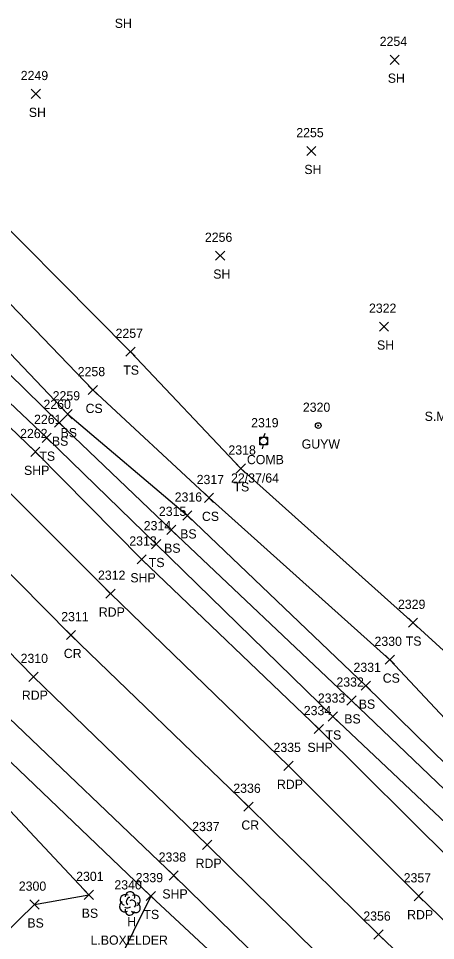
# Model space of a CAD drawing. Extents: x 1472233 to 1475777, y 540726 to 543442.
# Drawn here: x 1473588 to 1473678.6, y 542599.7 to 542800 of the extents above; entities that cross this region are included whole.
import ezdxf

# ---------------------------------------------------------------- set-up
doc = ezdxf.new("R2010")
doc.units = 0
for name, color, linetype in [('L_A', 7, 'Continuous'), ('L_C', 7, 'Continuous'), ('L_I', 7, 'Continuous'), ('L_TIC', 7, 'Continuous'), ('LELB', 7, 'Continuous'), ('LTD', 7, 'Continuous'), ('P_A', 7, 'Continuous'), ('P_I', 7, 'Continuous'), ('P_TIC', 7, 'Continuous'), ('PET', 7, 'Continuous'), ('PRC', 7, 'Continuous'), ('PSP', 7, 'Continuous'), ('U_A', 7, 'Continuous'), ('U_C', 7, 'Continuous'), ('U_I', 7, 'Continuous'), ('UP', 7, 'Continuous'), ('UPGW', 7, 'Continuous')]:
    doc.layers.add(name, color=color, linetype=linetype)

msp = doc.modelspace()

# ---------------------------------------------------------------- linework, layer by layer
at = {"layer": 'L_TIC'}
for points in [[(1473668.73, 542790.01), (1473670.73, 542792.01)], [(1473670.73, 542790.01), (1473668.73, 542792.01)], [(1473590.8, 542782.59), (1473592.8, 542784.59)], [(1473592.8, 542782.59), (1473590.8, 542784.59)], [(1473650.62, 542770.19), (1473652.62, 542772.19)], [(1473652.62, 542770.19), (1473650.62, 542772.19)], [(1473630.84, 542747.47), (1473632.84, 542749.47)], [(1473632.84, 542747.47), (1473630.84, 542749.47)], [(1473666.4, 542732.06), (1473668.4, 542734.06)], [(1473668.4, 542732.06), (1473666.4, 542734.06)], [(1473611.39, 542726.62), (1473613.39, 542728.62)], [(1473613.39, 542726.62), (1473611.39, 542728.62)], [(1473603.17, 542718.3), (1473605.17, 542720.3)], [(1473605.17, 542718.3), (1473603.17, 542720.3)], [(1473597.73, 542713.04), (1473599.73, 542715.04)], [(1473599.73, 542713.04), (1473597.73, 542715.04)], [(1473595.86, 542711.19), (1473597.86, 542713.19)], [(1473597.86, 542711.19), (1473595.86, 542713.19)], [(1473593.17, 542707.93), (1473595.17, 542709.93)], [(1473595.17, 542707.93), (1473593.17, 542709.93)], [(1473635.32, 542701.27), (1473637.32, 542703.27)], [(1473637.32, 542701.27), (1473635.32, 542703.27)], [(1473628.42, 542694.86), (1473630.42, 542696.86)], [(1473630.42, 542694.86), (1473628.42, 542696.86)], [(1473623.71, 542691.05), (1473625.71, 542693.05)], [(1473625.71, 542691.05), (1473623.71, 542693.05)], [(1473620.23, 542687.95), (1473622.23, 542689.95)], [(1473622.23, 542687.95), (1473620.23, 542689.95)], [(1473616.93, 542684.84), (1473618.93, 542686.84)], [(1473618.93, 542684.84), (1473616.93, 542686.84)], [(1473672.71, 542667.77), (1473674.71, 542669.77)], [(1473674.71, 542667.77), (1473672.71, 542669.77)], [(1473667.69, 542659.73), (1473669.69, 542661.73)], [(1473669.69, 542659.73), (1473667.69, 542661.73)], [(1473662.48, 542654.08), (1473664.48, 542656.08)], [(1473664.48, 542654.08), (1473662.48, 542656.08)], [(1473659.33, 542650.88), (1473661.33, 542652.88)], [(1473661.33, 542650.88), (1473659.33, 542652.88)], [(1473655.3, 542647.39), (1473657.3, 542649.39)], [(1473657.3, 542647.39), (1473655.3, 542649.39)], [(1473602.34, 542608.68), (1473604.34, 542610.68)], [(1473604.34, 542608.68), (1473602.34, 542610.68)], [(1473615.76, 542608.41), (1473617.76, 542610.41)], [(1473617.76, 542608.41), (1473615.76, 542610.41)], [(1473615.76, 542608.41), (1473617.76, 542610.41)], [(1473617.76, 542608.41), (1473615.76, 542610.41)], [(1473590.54, 542606.56), (1473592.54, 542608.56)], [(1473592.54, 542606.56), (1473590.54, 542608.56)]]:
    msp.add_lwpolyline(points, dxfattribs=at)
at = {"layer": 'LELB'}
for points in [[(1473533.67, 542804.55), (1473552.88, 542788.13), (1473556.88, 542785.23), (1473573.99, 542766.25), (1473612.39, 542727.62), (1473636.32, 542702.27), (1473673.71, 542668.77), (1473704.07, 542641.06), (1473731.53, 542612.73), (1473761.48, 542585.32), (1473782.29, 542564.92), (1473785.92, 542561.45), (1473799.65, 542550.04), (1473837.85, 542540.63), (1473852.25, 542543.24), (1473872.66, 542564.42), (1473894.27, 542588.71), (1473912.61, 542619.34)], [(1473525.71, 542797.41), (1473571.76, 542752.99), (1473604.17, 542719.3), (1473629.42, 542695.86), (1473668.69, 542660.73), (1473695.91, 542631.66), (1473722.49, 542604.9), (1473754.1, 542577.93), (1473792.77, 542542.66), (1473824.81, 542525.66)], [(1473520.98, 542792.82), (1473566.75, 542747.64), (1473598.73, 542714.04), (1473624.71, 542692.05), (1473663.48, 542655.08), (1473691.76, 542627.35), (1473719.38, 542602.08), (1473749.67, 542574.18), (1473788.77, 542538.46), (1473824.81, 542525.66), (1473852.8, 542532.76), (1473882.6, 542548.46), (1473905.87, 542578.34), (1473927.53, 542599.64)], [(1473518.4, 542790.01), (1473563.89, 542744.47), (1473596.86, 542712.19), (1473621.23, 542688.95), (1473660.33, 542651.88), (1473689.02, 542624.42), (1473715.73, 542598.61), (1473746.44, 542571.32), (1473784.75, 542534.69), (1473817.99, 542514.69), (1473848.43, 542502.42), (1473876.97, 542512.66), (1473897.43, 542533.79), (1473923.6, 542558.96), (1473938.44, 542588.81), (1473927.53, 542599.64)], [(1473514.27, 542786.32), (1473560.24, 542740.99), (1473594.17, 542708.93), (1473617.93, 542685.84), (1473656.3, 542648.39), (1473686.09, 542620.25), (1473711.9, 542594.5), (1473742.08, 542567.84), (1473780.05, 542529.89), (1473807.97, 542506.72), (1473829.24, 542487.77), (1473845.46, 542486.06), (1473857.71, 542489.19), (1473866.44, 542494.63), (1473880.47, 542509.49), (1473900.34, 542530.71), (1473925.82, 542557.03), (1473946.47, 542580.98), (1473946.59, 542594.08), (1473931.4, 542613.43), (1473912.61, 542619.34)], [(1473565.52, 542656.42), (1473579.67, 542644.83), (1473616.76, 542609.41), (1473646.96, 542581.33), (1473673.23, 542554.38), (1473676.6, 542547.7)], [(1473566.89, 542528.89), (1473564.41, 542543.6), (1473559.82, 542572.3), (1473573.83, 542590.3), (1473591.54, 542607.56), (1473603.34, 542609.68), (1473581.89, 542632.49), (1473565.16, 542641.39)], [(1473616.76, 542609.41), (1473601.51, 542578.57), (1473587.91, 542551.82), (1473580.91, 542527.84)]]:
    msp.add_lwpolyline(points, dxfattribs=at)
at = {"layer": 'LTD'}
msp.add_line((1473612.22, 542607.84), (1473612.22, 542607.84), dxfattribs=at)
msp.add_line((1473612.22, 542607.84), (1473612.22, 542607.84), dxfattribs=at)
msp.add_arc((1473612.27, 542609.28), 1.05, 335.5272, 180.9563, dxfattribs=at)
for centre, major_axis, ratio, start_param, end_param in [((1473611.14, 542607.14), (0.58, -1.04), 0.959034, 3.141593, 6.283185), ((1473611.43, 542608.51), (1.21, -0.51), 0.895232, 1.570796, 4.712389), ((1473612.01, 542608.3), (-0.208, -0.792), 0.645439, 3.141593, 6.283185), ((1473612.72, 542607.68), (-0.5, 0.667), 0.989748, 3.141593, 6.283185), ((1473613.26, 542608.43), (-1.14, -0.48), 0.949671, 1.570796, 4.712389), ((1473612.22, 542606.34), (0.26, 1.06), 0.942809, 1.570796, 4.712389), ((1473611.76, 542607.09), (-0.625, -0.083), 0.423636, 0, 3.141593), ((1473613.22, 542607.01), (-1.09, 0.79), 0.841452, 1.570796, 4.712389)]:
    msp.add_ellipse(centre, major_axis=major_axis, ratio=ratio, start_param=start_param, end_param=end_param, dxfattribs=at)
at = {"layer": 'P_TIC'}
for points in [[(1473590.71, 542704.85), (1473592.71, 542706.85)], [(1473592.71, 542704.85), (1473590.71, 542706.85)], [(1473613.8, 542681.52), (1473615.8, 542683.52)], [(1473615.8, 542681.52), (1473613.8, 542683.52)], [(1473607.01, 542674.08), (1473609.01, 542676.08)], [(1473609.01, 542674.08), (1473607.01, 542676.08)], [(1473598.45, 542665.09), (1473600.45, 542667.09)], [(1473600.45, 542665.09), (1473598.45, 542667.09)], [(1473590.29, 542656.02), (1473592.29, 542658.02)], [(1473592.29, 542656.02), (1473590.29, 542658.02)], [(1473652.25, 542644.69), (1473654.25, 542646.69)], [(1473654.25, 542644.69), (1473652.25, 542646.69)], [(1473645.67, 542636.68), (1473647.67, 542638.68)], [(1473647.67, 542636.68), (1473645.67, 542638.68)], [(1473637, 542627.82), (1473639, 542629.82)], [(1473639, 542627.82), (1473637, 542629.82)], [(1473628.02, 542619.51), (1473630.02, 542621.51)], [(1473630.02, 542619.51), (1473628.02, 542621.51)], [(1473620.74, 542612.87), (1473622.74, 542614.87)], [(1473622.74, 542612.87), (1473620.74, 542614.87)], [(1473673.93, 542608.37), (1473675.93, 542610.37)], [(1473675.93, 542608.37), (1473673.93, 542610.37)], [(1473665.22, 542600.06), (1473667.22, 542602.06)], [(1473667.22, 542600.06), (1473665.22, 542602.06)]]:
    msp.add_lwpolyline(points, dxfattribs=at)
at = {"layer": 'PET'}
for points in [[(1473504.62, 542776.33), (1473550.32, 542731.61), (1473584.84, 542698.3), (1473608.01, 542675.08), (1473646.67, 542637.68), (1473674.93, 542609.37), (1473701.59, 542583.63), (1473729.62, 542555.98), (1473768.46, 542518.15), (1473803.13, 542483.63), (1473835.24, 542452.12), (1473854.12, 542434.15), (1473878.03, 542410.14), (1473913.11, 542376.24), (1473951.32, 542338.39), (1473966.93, 542323.54), (1474008.37, 542283), (1474040.51, 542251.21), (1474079.09, 542215.26), (1474152.53, 542143.43), (1474186.7, 542109.47), (1474221.34, 542076.07), (1474257.17, 542041.35)], [(1473486.93, 542759.48), (1473533.41, 542713.5), (1473568.24, 542680.61), (1473591.29, 542657.02), (1473629.02, 542620.51), (1473657.65, 542592.3), (1473684.65, 542566.35), (1473712.07, 542539.16), (1473750.99, 542501.36), (1473781.95, 542470.51), (1473816.78, 542436.69), (1473836.91, 542417.28), (1473859.76, 542394.19), (1473895.18, 542360.02), (1473933.99, 542321.38), (1473950.56, 542305.13), (1473990.91, 542266.49), (1474025.14, 542233.4), (1474060.45, 542198.14), (1474133.98, 542127.35), (1474169.03, 542092.64), (1474239.7, 542023.8)]]:
    msp.add_lwpolyline(points, dxfattribs=at)
at = {"layer": 'PRC'}
msp.add_lwpolyline([(1473496.06, 542767.15), (1473541.59, 542723.23), (1473576.69, 542689.04), (1473599.45, 542666.09), (1473638, 542628.82), (1473666.22, 542601.06), (1473693.18, 542575.28), (1473720.82, 542547.73), (1473759.64, 542509.32), (1473791.5, 542477.44), (1473825.51, 542444.45), (1473844.96, 542425.29), (1473869.12, 542402.24), (1473904.25, 542367.71), (1473942.02, 542329.58), (1473959.56, 542314.37), (1473999.68, 542274.85), (1474033.6, 542242.12), (1474069.35, 542206.93), (1474143.1, 542135.36), (1474177.51, 542101.4), (1474248.4, 542032.72)], dxfattribs=at)
at = {"layer": 'PSP'}
for points in [[(1473511.53, 542783.65), (1473557.71, 542738.52), (1473591.71, 542705.85), (1473614.8, 542682.52), (1473653.25, 542645.69), (1473682.39, 542616.78), (1473708.77, 542591.71), (1473737.42, 542563.39), (1473776.1, 542525.9), (1473801.03, 542501.12), (1473821.16, 542481.55), (1473851.91, 542452.04), (1473882.06, 542422.12), (1473920.54, 542384.18), (1473958.97, 542346.58), (1473974.8, 542332.02), (1474016, 542291.37), (1474048.58, 542260.06), (1474087.68, 542221.94), (1474123.03, 542187.8), (1474161.37, 542151.41), (1474230.43, 542083.96), (1474265.44, 542049.86)], [(1473477.23, 542750.94), (1473505.7, 542725.54), (1473535.93, 542696.72), (1473560.62, 542672.69), (1473579.24, 542654.93), (1473584.38, 542649.62), (1473621.74, 542613.87), (1473650.73, 542585.54), (1473678.25, 542559.11), (1473685.14, 542552.29), (1473704.13, 542532.51), (1473743.26, 542493.38), (1473766.11, 542471.02), (1473782.02, 542455.83), (1473809.5, 542428.66), (1473828.97, 542409.61), (1473851.62, 542386.5)]]:
    msp.add_lwpolyline(points, dxfattribs=at)
at = {"layer": 'UP'}
for p, q in [((1473640.43, 542707.36), (1473640.43, 542709.02)), ((1473640.43, 542709.02), (1473642.09, 542709.02)), ((1473641.51, 542709.86), (1473641.26, 542709.02)), ((1473641.26, 542708.19), (1473641.26, 542708.19)), ((1473642.09, 542709.02), (1473642.09, 542707.36)), ((1473642.09, 542707.36), (1473640.43, 542707.36)), ((1473641.01, 542706.52), (1473641.26, 542707.36))]:
    msp.add_line(p, q, dxfattribs=at)
msp.add_circle((1473641.26, 542708.19), 0.833, dxfattribs=at)
at = {"layer": 'UPGW'}
for radius in [0.625, 0.0833]:
    msp.add_circle((1473653.13, 542711.56), radius, dxfattribs=at)

# ---------------------------------------------------------------- texts
at = {"layer": 'L_A'}
for s, p in [('SH', (1473608.95, 542797.93)), ('SH', (1473668.22, 542786.01)), ('SH', (1473590.29, 542778.59)), ('SH', (1473650.11, 542766.19)), ('SH', (1473630.33, 542743.47)), ('SH', (1473665.89, 542728.06)), ('TS', (1473610.8, 542722.62)), ('CS', (1473602.61, 542714.3)), ('BS', (1473597.18, 542709.04)), ('BS', (1473595.3, 542707.19)), ('TS', (1473592.58, 542703.93)), ('TS', (1473634.73, 542697.27)), ('CS', (1473627.87, 542690.86)), ('BS', (1473623.15, 542687.05)), ('BS', (1473619.67, 542683.95)), ('TS', (1473616.34, 542680.84)), ('TS', (1473672.12, 542663.77)), ('CS', (1473667.13, 542655.73)), ('BS', (1473661.92, 542650.08)), ('BS', (1473658.77, 542646.88)), ('TS', (1473654.71, 542643.39)), ('BS', (1473601.78, 542604.68)), ('TS', (1473615.17, 542604.41)), ('TS', (1473615.17, 542604.41)), ('BS', (1473589.98, 542602.56)), ('H', (1473611.65, 542602.84))]:
    msp.add_text(s, height=2, dxfattribs=at).set_placement(p)
at = {"layer": 'L_C'}
for s, p in [('S.MAPLE', (1473676.23, 542712.59)), ('L.BOXELDER', (1473603.69, 542598.84))]:
    msp.add_text(s, height=2, dxfattribs=at).set_placement(p)
at = {"layer": 'L_I'}
for s, p in [('2254', (1473666.47, 542794.01)), ('2249', (1473588.54, 542786.59)), ('2255', (1473648.36, 542774.19)), ('2256', (1473628.52, 542751.47)), ('2322', (1473664.14, 542736.06)), ('2257', (1473609.13, 542730.62)), ('2258', (1473600.91, 542722.3)), ('2259', (1473595.47, 542717.04)), ('2260', (1473593.47, 542715.19)), ('2261', (1473591.43, 542711.93)), ('2318', (1473633.63, 542705.27)), ('2317', (1473626.73, 542698.86)), ('2316', (1473621.96, 542695.05)), ('2315', (1473618.53, 542691.95)), ('2314', (1473615.24, 542688.84)), ('2329', (1473670.44, 542671.77)), ('2330', (1473665.34, 542663.73)), ('2331', (1473660.78, 542658.08)), ('2332', (1473657.07, 542654.88)), ('2333', (1473653.04, 542651.39)), ('2301', (1473600.57, 542612.68)), ('2339', (1473613.49, 542612.41)), ('2339', (1473613.49, 542612.41)), ('2300', (1473588.12, 542610.56)), ('2340', (1473608.87, 542610.84))]:
    msp.add_text(s, height=2, dxfattribs=at).set_placement(p)
at = {"layer": 'P_A'}
for s, p in [('SHP', (1473589.25, 542700.85)), ('SHP', (1473612.34, 542677.52)), ('RDP', (1473605.49, 542670.08)), ('CR', (1473597.89, 542661.09)), ('RDP', (1473588.78, 542652.02)), ('SHP', (1473650.78, 542640.69)), ('RDP', (1473644.16, 542632.68)), ('CR', (1473636.44, 542623.82)), ('RDP', (1473626.5, 542615.51)), ('SHP', (1473619.28, 542608.87)), ('RDP', (1473672.42, 542604.37))]:
    msp.add_text(s, height=2, dxfattribs=at).set_placement(p)
at = {"layer": 'P_I'}
for s, p in [('2262', (1473588.4, 542708.85)), ('2313', (1473612.11, 542685.52)), ('2312', (1473605.31, 542678.08)), ('2311', (1473597.33, 542669.09)), ('2310', (1473588.51, 542660.02)), ('2334', (1473649.99, 542648.69)), ('2335', (1473643.41, 542640.68)), ('2336', (1473634.69, 542631.82)), ('2337', (1473625.76, 542623.51)), ('2338', (1473618.48, 542616.87)), ('2357', (1473671.67, 542612.37)), ('2356', (1473662.91, 542604.06))]:
    msp.add_text(s, height=2, dxfattribs=at).set_placement(p)
at = {"layer": 'U_A'}
for s, p in [('GUYW', (1473649.53, 542706.56)), ('COMB', (1473637.64, 542703.19))]:
    msp.add_text(s, height=2, dxfattribs=at).set_placement(p)
at = {"layer": 'U_C'}
msp.add_text('22/37/64', height=2, dxfattribs=at).set_placement((1473634.2, 542699.19))
at = {"layer": 'U_I'}
for s, p in [('2320', (1473649.79, 542714.56)), ('2319', (1473638.56, 542711.19))]:
    msp.add_text(s, height=2, dxfattribs=at).set_placement(p)

doc.saveas('drawing.dxf')
